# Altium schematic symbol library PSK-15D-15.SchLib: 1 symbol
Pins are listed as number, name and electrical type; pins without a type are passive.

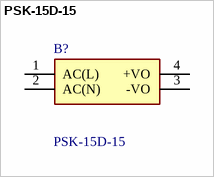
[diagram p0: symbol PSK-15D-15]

## PSK-15D-15
designator B?
AC/DC Power Modules ac-dc, 15 W, 15 Vdc, single output, encapsulated PCB, 85~305 Vac; Manufacturer_Name: CUI Inc.; Geometry.Height: 24mm
footprint PSK15D15
pins: 1 AC(L), 2 AC(N), 3 -VO, 4 +VO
